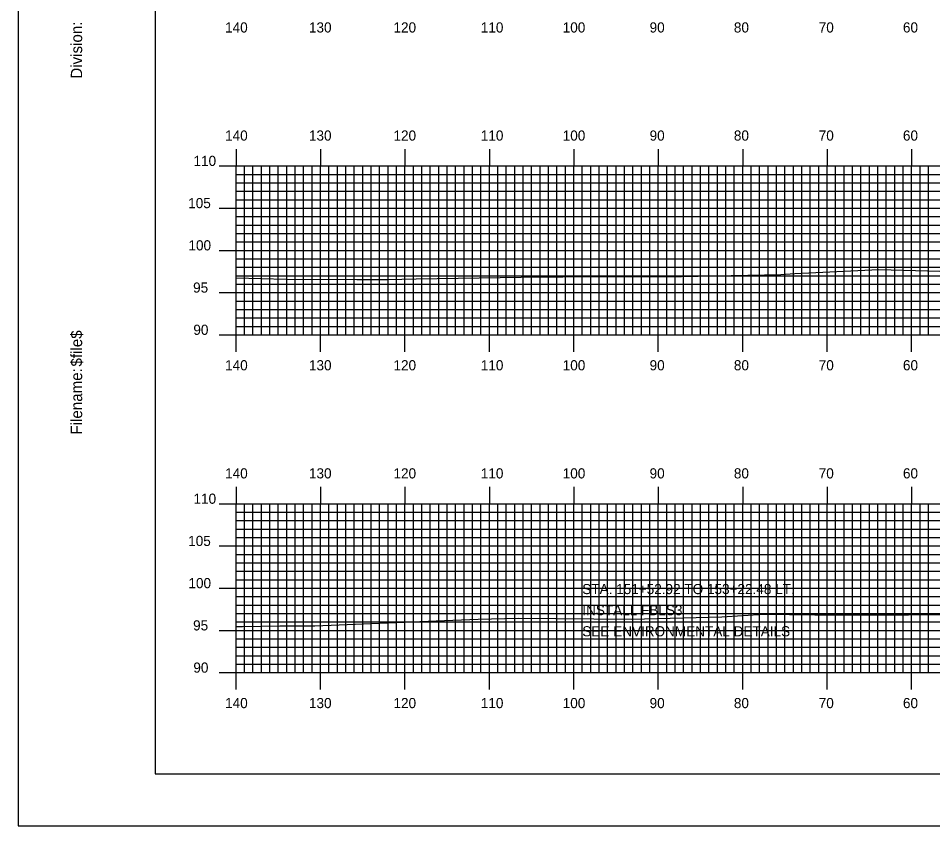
# Model space of a CAD drawing. Extents: x 1778712 to 1779055, y 442591 to 442811.
# Drawn here: x 1778712 to 1778820.3, y 442590.5 to 442686.2 of the extents above; entities that cross this region are included whole.
import ezdxf

# ---------------------------------------------------------------- set-up
doc = ezdxf.new("R2010")
doc.units = 0
for name, color, linetype in [('BORDER', 7, 'Continuous'), ('D_Text_Standard', 7, 'Continuous'), ('H_V ANNOTATION', 7, 'Continuous'), ('MAJOR', 7, 'Continuous'), ('MINOR', 7, 'Continuous'), ('PLOT BOUNDARY', 7, 'Continuous'), ('S_Roadway_Centerline', 7, 'Continuous')]:
    doc.layers.add(name, color=color, linetype=linetype)

msp = doc.modelspace()

# ---------------------------------------------------------------- linework, layer by layer
at = {"layer": 'BORDER'}
msp.add_lwpolyline([(1778728.22, 442596.67), (1779048.22, 442596.67), (1779048.22, 442806.67), (1778728.22, 442806.67)], close=True, dxfattribs=at)
at = {"layer": 'MAJOR'}
for p, q in [((1778737.82, 442670.67), (1778737.82, 442668.67)), ((1778747.82, 442670.67), (1778747.82, 442668.67)), ((1778757.82, 442670.67), (1778757.82, 442668.67)), ((1778767.82, 442670.67), (1778767.82, 442668.67)), ((1778777.82, 442670.67), (1778777.82, 442668.67)), ((1778787.82, 442670.67), (1778787.82, 442668.67)), ((1778797.82, 442670.67), (1778797.82, 442668.67)), ((1778807.82, 442670.67), (1778807.82, 442668.67)), ((1778817.82, 442670.67), (1778817.82, 442668.67)), ((1778735.81, 442668.67), (1778737.82, 442668.67)), ((1778737.82, 442668.67), (1779017.82, 442668.67)), ((1778737.82, 442648.67), (1778737.82, 442668.67)), ((1778737.82, 442648.67), (1778737.82, 442668.67)), ((1778737.82, 442668.67), (1779017.82, 442668.67)), ((1778747.82, 442648.67), (1778747.82, 442668.67)), ((1778757.82, 442648.67), (1778757.82, 442668.67)), ((1778767.82, 442648.67), (1778767.82, 442668.67)), ((1778777.82, 442648.67), (1778777.82, 442668.67)), ((1778787.82, 442648.67), (1778787.82, 442668.67)), ((1778797.82, 442648.67), (1778797.82, 442668.67)), ((1778807.82, 442648.67), (1778807.82, 442668.67)), ((1778817.82, 442648.67), (1778817.82, 442668.67)), ((1778735.81, 442663.67), (1778737.82, 442663.67)), ((1778737.82, 442663.67), (1779017.82, 442663.67)), ((1778735.81, 442658.67), (1778737.82, 442658.67)), ((1778737.82, 442658.67), (1779017.82, 442658.67)), ((1778735.81, 442653.67), (1778737.82, 442653.67)), ((1778737.82, 442653.67), (1779017.82, 442653.67)), ((1778735.81, 442648.67), (1778737.82, 442648.67)), ((1778737.82, 442648.67), (1779017.82, 442648.67)), ((1778737.82, 442648.67), (1779017.82, 442648.67)), ((1778737.82, 442646.66), (1778737.82, 442648.67)), ((1778747.82, 442646.66), (1778747.82, 442648.67)), ((1778757.82, 442646.66), (1778757.82, 442648.67)), ((1778767.82, 442646.66), (1778767.82, 442648.67)), ((1778777.82, 442646.66), (1778777.82, 442648.67)), ((1778787.82, 442646.66), (1778787.82, 442648.67)), ((1778797.82, 442646.66), (1778797.82, 442648.67)), ((1778807.82, 442646.66), (1778807.82, 442648.67)), ((1778817.82, 442646.66), (1778817.82, 442648.67)), ((1778737.82, 442630.67), (1778737.82, 442628.67)), ((1778747.82, 442630.67), (1778747.82, 442628.67)), ((1778757.82, 442630.67), (1778757.82, 442628.67)), ((1778767.82, 442630.67), (1778767.82, 442628.67)), ((1778777.82, 442630.67), (1778777.82, 442628.67)), ((1778787.82, 442630.67), (1778787.82, 442628.67)), ((1778797.82, 442630.67), (1778797.82, 442628.67)), ((1778807.82, 442630.67), (1778807.82, 442628.67)), ((1778817.82, 442630.67), (1778817.82, 442628.67)), ((1778735.81, 442628.67), (1778737.82, 442628.67)), ((1778737.82, 442628.67), (1779017.82, 442628.67)), ((1778737.82, 442608.67), (1778737.82, 442628.67)), ((1778737.82, 442608.67), (1778737.82, 442628.67)), ((1778737.82, 442628.67), (1779017.82, 442628.67)), ((1778747.82, 442608.67), (1778747.82, 442628.67)), ((1778757.82, 442608.67), (1778757.82, 442628.67)), ((1778767.82, 442608.67), (1778767.82, 442628.67)), ((1778777.82, 442608.67), (1778777.82, 442628.67)), ((1778787.82, 442608.67), (1778787.82, 442628.67)), ((1778797.82, 442608.67), (1778797.82, 442628.67)), ((1778807.82, 442608.67), (1778807.82, 442628.67)), ((1778817.82, 442608.67), (1778817.82, 442628.67)), ((1778735.81, 442623.67), (1778737.82, 442623.67)), ((1778737.82, 442623.67), (1779017.82, 442623.67)), ((1778735.81, 442618.67), (1778737.82, 442618.67)), ((1778737.82, 442618.67), (1779017.82, 442618.67)), ((1778735.81, 442613.67), (1778737.82, 442613.67)), ((1778737.82, 442613.67), (1779017.82, 442613.67)), ((1778735.81, 442608.67), (1778737.82, 442608.67)), ((1778737.82, 442608.67), (1779017.82, 442608.67)), ((1778737.82, 442608.67), (1779017.82, 442608.67)), ((1778737.82, 442606.66), (1778737.82, 442608.67)), ((1778747.82, 442606.66), (1778747.82, 442608.67)), ((1778757.82, 442606.66), (1778757.82, 442608.67)), ((1778767.82, 442606.66), (1778767.82, 442608.67)), ((1778777.82, 442606.66), (1778777.82, 442608.67)), ((1778787.82, 442606.66), (1778787.82, 442608.67)), ((1778797.82, 442606.66), (1778797.82, 442608.67)), ((1778807.82, 442606.66), (1778807.82, 442608.67)), ((1778817.82, 442606.66), (1778817.82, 442608.67))]:
    msp.add_line(p, q, dxfattribs=at)
at = {"layer": 'MINOR'}
for p, q in [((1778738.82, 442648.67), (1778738.82, 442668.67)), ((1778739.82, 442648.67), (1778739.82, 442668.67)), ((1778740.82, 442648.67), (1778740.82, 442668.67)), ((1778741.82, 442648.67), (1778741.82, 442668.67)), ((1778742.82, 442648.67), (1778742.82, 442668.67)), ((1778743.82, 442648.67), (1778743.82, 442668.67)), ((1778744.82, 442648.67), (1778744.82, 442668.67)), ((1778745.82, 442648.67), (1778745.82, 442668.67)), ((1778746.82, 442648.67), (1778746.82, 442668.67)), ((1778748.82, 442648.67), (1778748.82, 442668.67)), ((1778749.82, 442648.67), (1778749.82, 442668.67)), ((1778750.82, 442648.67), (1778750.82, 442668.67)), ((1778751.82, 442648.67), (1778751.82, 442668.67)), ((1778752.82, 442648.67), (1778752.82, 442668.67)), ((1778753.82, 442648.67), (1778753.82, 442668.67)), ((1778754.82, 442648.67), (1778754.82, 442668.67)), ((1778755.82, 442648.67), (1778755.82, 442668.67)), ((1778756.82, 442648.67), (1778756.82, 442668.67)), ((1778758.82, 442648.67), (1778758.82, 442668.67)), ((1778759.82, 442648.67), (1778759.82, 442668.67)), ((1778760.82, 442648.67), (1778760.82, 442668.67)), ((1778761.82, 442648.67), (1778761.82, 442668.67)), ((1778762.82, 442648.67), (1778762.82, 442668.67)), ((1778763.82, 442648.67), (1778763.82, 442668.67)), ((1778764.82, 442648.67), (1778764.82, 442668.67)), ((1778765.82, 442648.67), (1778765.82, 442668.67)), ((1778766.82, 442648.67), (1778766.82, 442668.67)), ((1778768.82, 442648.67), (1778768.82, 442668.67)), ((1778769.82, 442648.67), (1778769.82, 442668.67)), ((1778770.82, 442648.67), (1778770.82, 442668.67)), ((1778771.82, 442648.67), (1778771.82, 442668.67)), ((1778772.82, 442648.67), (1778772.82, 442668.67)), ((1778773.82, 442648.67), (1778773.82, 442668.67)), ((1778774.82, 442648.67), (1778774.82, 442668.67)), ((1778775.82, 442648.67), (1778775.82, 442668.67)), ((1778776.82, 442648.67), (1778776.82, 442668.67)), ((1778778.82, 442648.67), (1778778.82, 442668.67)), ((1778779.82, 442648.67), (1778779.82, 442668.67)), ((1778780.82, 442648.67), (1778780.82, 442668.67)), ((1778781.82, 442648.67), (1778781.82, 442668.67)), ((1778782.82, 442648.67), (1778782.82, 442668.67)), ((1778783.82, 442648.67), (1778783.82, 442668.67)), ((1778784.82, 442648.67), (1778784.82, 442668.67)), ((1778785.82, 442648.67), (1778785.82, 442668.67)), ((1778786.82, 442648.67), (1778786.82, 442668.67)), ((1778788.82, 442648.67), (1778788.82, 442668.67)), ((1778789.82, 442648.67), (1778789.82, 442668.67)), ((1778790.82, 442648.67), (1778790.82, 442668.67)), ((1778791.82, 442648.67), (1778791.82, 442668.67)), ((1778792.82, 442648.67), (1778792.82, 442668.67)), ((1778793.82, 442648.67), (1778793.82, 442668.67)), ((1778794.82, 442648.67), (1778794.82, 442668.67)), ((1778795.82, 442648.67), (1778795.82, 442668.67)), ((1778796.82, 442648.67), (1778796.82, 442668.67)), ((1778798.82, 442648.67), (1778798.82, 442668.67)), ((1778799.82, 442648.67), (1778799.82, 442668.67)), ((1778800.82, 442648.67), (1778800.82, 442668.67)), ((1778801.82, 442648.67), (1778801.82, 442668.67)), ((1778802.82, 442648.67), (1778802.82, 442668.67)), ((1778803.82, 442648.67), (1778803.82, 442668.67)), ((1778804.82, 442648.67), (1778804.82, 442668.67)), ((1778805.82, 442648.67), (1778805.82, 442668.67)), ((1778806.82, 442648.67), (1778806.82, 442668.67)), ((1778808.82, 442648.67), (1778808.82, 442668.67)), ((1778809.82, 442648.67), (1778809.82, 442668.67)), ((1778810.82, 442648.67), (1778810.82, 442668.67)), ((1778811.82, 442648.67), (1778811.82, 442668.67)), ((1778812.82, 442648.67), (1778812.82, 442668.67)), ((1778813.82, 442648.67), (1778813.82, 442668.67)), ((1778814.82, 442648.67), (1778814.82, 442668.67)), ((1778815.82, 442648.67), (1778815.82, 442668.67)), ((1778816.82, 442648.67), (1778816.82, 442668.67)), ((1778818.82, 442648.67), (1778818.82, 442668.67)), ((1778819.82, 442648.67), (1778819.82, 442668.67)), ((1778737.82, 442667.67), (1779017.82, 442667.67)), ((1778737.82, 442667.67), (1778739.82, 442667.67)), ((1778737.82, 442666.67), (1779017.82, 442666.67)), ((1778737.82, 442666.67), (1778739.82, 442666.67)), ((1778737.82, 442665.67), (1779017.82, 442665.67)), ((1778737.82, 442665.67), (1778739.82, 442665.67)), ((1778737.82, 442664.67), (1779017.82, 442664.67)), ((1778737.82, 442664.67), (1778739.82, 442664.67)), ((1778737.82, 442662.67), (1779017.82, 442662.67)), ((1778737.82, 442662.67), (1778739.82, 442662.67)), ((1778737.82, 442661.67), (1779017.82, 442661.67)), ((1778737.82, 442661.67), (1778739.82, 442661.67)), ((1778737.82, 442660.67), (1779017.82, 442660.67)), ((1778737.82, 442660.67), (1778739.82, 442660.67)), ((1778737.82, 442659.67), (1779017.82, 442659.67)), ((1778737.82, 442659.67), (1778739.82, 442659.67)), ((1778737.82, 442657.67), (1779017.82, 442657.67)), ((1778737.82, 442657.67), (1778739.82, 442657.67)), ((1778737.82, 442656.67), (1779017.82, 442656.67)), ((1778737.82, 442656.67), (1778739.82, 442656.67)), ((1778737.82, 442655.67), (1779017.82, 442655.67)), ((1778737.82, 442655.67), (1778739.82, 442655.67)), ((1778737.82, 442654.67), (1779017.82, 442654.67)), ((1778737.82, 442654.67), (1778739.82, 442654.67)), ((1778737.82, 442652.67), (1779017.82, 442652.67)), ((1778737.82, 442652.67), (1778739.82, 442652.67)), ((1778737.82, 442651.67), (1779017.82, 442651.67)), ((1778737.82, 442651.67), (1778739.82, 442651.67)), ((1778737.82, 442650.67), (1779017.82, 442650.67)), ((1778737.82, 442650.67), (1778739.82, 442650.67)), ((1778737.82, 442649.67), (1779017.82, 442649.67)), ((1778737.82, 442649.67), (1778739.82, 442649.67)), ((1778738.82, 442608.67), (1778738.82, 442628.67)), ((1778739.82, 442608.67), (1778739.82, 442628.67)), ((1778740.82, 442608.67), (1778740.82, 442628.67)), ((1778741.82, 442608.67), (1778741.82, 442628.67)), ((1778742.82, 442608.67), (1778742.82, 442628.67)), ((1778743.82, 442608.67), (1778743.82, 442628.67)), ((1778744.82, 442608.67), (1778744.82, 442628.67)), ((1778745.82, 442608.67), (1778745.82, 442628.67)), ((1778746.82, 442608.67), (1778746.82, 442628.67)), ((1778748.82, 442608.67), (1778748.82, 442628.67)), ((1778749.82, 442608.67), (1778749.82, 442628.67)), ((1778750.82, 442608.67), (1778750.82, 442628.67)), ((1778751.82, 442608.67), (1778751.82, 442628.67)), ((1778752.82, 442608.67), (1778752.82, 442628.67)), ((1778753.82, 442608.67), (1778753.82, 442628.67)), ((1778754.82, 442608.67), (1778754.82, 442628.67)), ((1778755.82, 442608.67), (1778755.82, 442628.67)), ((1778756.82, 442608.67), (1778756.82, 442628.67)), ((1778758.82, 442608.67), (1778758.82, 442628.67)), ((1778759.82, 442608.67), (1778759.82, 442628.67)), ((1778760.82, 442608.67), (1778760.82, 442628.67)), ((1778761.82, 442608.67), (1778761.82, 442628.67)), ((1778762.82, 442608.67), (1778762.82, 442628.67)), ((1778763.82, 442608.67), (1778763.82, 442628.67)), ((1778764.82, 442608.67), (1778764.82, 442628.67)), ((1778765.82, 442608.67), (1778765.82, 442628.67)), ((1778766.82, 442608.67), (1778766.82, 442628.67)), ((1778768.82, 442608.67), (1778768.82, 442628.67)), ((1778769.82, 442608.67), (1778769.82, 442628.67)), ((1778770.82, 442608.67), (1778770.82, 442628.67)), ((1778771.82, 442608.67), (1778771.82, 442628.67)), ((1778772.82, 442608.67), (1778772.82, 442628.67)), ((1778773.82, 442608.67), (1778773.82, 442628.67)), ((1778774.82, 442608.67), (1778774.82, 442628.67)), ((1778775.82, 442608.67), (1778775.82, 442628.67)), ((1778776.82, 442608.67), (1778776.82, 442628.67)), ((1778778.82, 442608.67), (1778778.82, 442628.67)), ((1778779.82, 442608.67), (1778779.82, 442628.67)), ((1778780.82, 442608.67), (1778780.82, 442628.67)), ((1778781.82, 442608.67), (1778781.82, 442628.67)), ((1778782.82, 442608.67), (1778782.82, 442628.67)), ((1778783.82, 442608.67), (1778783.82, 442628.67)), ((1778784.82, 442608.67), (1778784.82, 442628.67)), ((1778785.82, 442608.67), (1778785.82, 442628.67)), ((1778786.82, 442608.67), (1778786.82, 442628.67)), ((1778788.82, 442608.67), (1778788.82, 442628.67)), ((1778789.82, 442608.67), (1778789.82, 442628.67)), ((1778790.82, 442608.67), (1778790.82, 442628.67)), ((1778791.82, 442608.67), (1778791.82, 442628.67)), ((1778792.82, 442608.67), (1778792.82, 442628.67)), ((1778793.82, 442608.67), (1778793.82, 442628.67)), ((1778794.82, 442608.67), (1778794.82, 442628.67)), ((1778795.82, 442608.67), (1778795.82, 442628.67)), ((1778796.82, 442608.67), (1778796.82, 442628.67)), ((1778798.82, 442608.67), (1778798.82, 442628.67)), ((1778799.82, 442608.67), (1778799.82, 442628.67)), ((1778800.82, 442608.67), (1778800.82, 442628.67)), ((1778801.82, 442608.67), (1778801.82, 442628.67)), ((1778802.82, 442608.67), (1778802.82, 442628.67)), ((1778803.82, 442608.67), (1778803.82, 442628.67)), ((1778804.82, 442608.67), (1778804.82, 442628.67)), ((1778805.82, 442608.67), (1778805.82, 442628.67)), ((1778806.82, 442608.67), (1778806.82, 442628.67)), ((1778808.82, 442608.67), (1778808.82, 442628.67)), ((1778809.82, 442608.67), (1778809.82, 442628.67)), ((1778810.82, 442608.67), (1778810.82, 442628.67)), ((1778811.82, 442608.67), (1778811.82, 442628.67)), ((1778812.82, 442608.67), (1778812.82, 442628.67)), ((1778813.82, 442608.67), (1778813.82, 442628.67)), ((1778814.82, 442608.67), (1778814.82, 442628.67)), ((1778815.82, 442608.67), (1778815.82, 442628.67)), ((1778816.82, 442608.67), (1778816.82, 442628.67)), ((1778818.82, 442608.67), (1778818.82, 442628.67)), ((1778819.82, 442608.67), (1778819.82, 442628.67)), ((1778737.82, 442627.67), (1779017.82, 442627.67)), ((1778737.82, 442627.67), (1778739.82, 442627.67)), ((1778737.82, 442626.67), (1779017.82, 442626.67)), ((1778737.82, 442626.67), (1778739.82, 442626.67)), ((1778737.82, 442625.67), (1779017.82, 442625.67)), ((1778737.82, 442625.67), (1778739.82, 442625.67)), ((1778737.82, 442624.67), (1779017.82, 442624.67)), ((1778737.82, 442624.67), (1778739.82, 442624.67)), ((1778737.82, 442622.67), (1779017.82, 442622.67)), ((1778737.82, 442622.67), (1778739.82, 442622.67)), ((1778737.82, 442621.67), (1779017.82, 442621.67)), ((1778737.82, 442621.67), (1778739.82, 442621.67)), ((1778737.82, 442620.67), (1779017.82, 442620.67)), ((1778737.82, 442620.67), (1778739.82, 442620.67)), ((1778737.82, 442619.67), (1779017.82, 442619.67)), ((1778737.82, 442619.67), (1778739.82, 442619.67)), ((1778737.82, 442617.67), (1779017.82, 442617.67)), ((1778737.82, 442617.67), (1778739.82, 442617.67)), ((1778737.82, 442616.67), (1779017.82, 442616.67)), ((1778737.82, 442616.67), (1778739.82, 442616.67)), ((1778737.82, 442615.67), (1779017.82, 442615.67)), ((1778737.82, 442615.67), (1778739.82, 442615.67)), ((1778737.82, 442614.67), (1779017.82, 442614.67)), ((1778737.82, 442614.67), (1778739.82, 442614.67)), ((1778737.82, 442612.67), (1779017.82, 442612.67)), ((1778737.82, 442612.67), (1778739.82, 442612.67)), ((1778737.82, 442611.67), (1779017.82, 442611.67)), ((1778737.82, 442611.67), (1778739.82, 442611.67)), ((1778737.82, 442610.67), (1779017.82, 442610.67)), ((1778737.82, 442610.67), (1778739.82, 442610.67)), ((1778737.82, 442609.67), (1779017.82, 442609.67)), ((1778737.82, 442609.67), (1778739.82, 442609.67))]:
    msp.add_line(p, q, dxfattribs=at)
at = {"layer": 'PLOT BOUNDARY'}
msp.add_lwpolyline([(1778712.03, 442590.55), (1779052.03, 442590.55), (1779052.03, 442810.55), (1778712.03, 442810.55)], close=True, dxfattribs=at)
at = {"layer": 'S_Roadway_Centerline'}
for points in [[(1778737.82, 442655.41), (1778743.77, 442655.28), (1778752.12, 442655.24), (1778755.74, 442655.24), (1778759.16, 442655.3), (1778771.59, 442655.5), (1778781.49, 442655.56), (1778790.56, 442655.57), (1778800.38, 442655.77), (1778802.33, 442655.8), (1778803.98, 442655.93), (1778813.95, 442656.4), (1778826.91, 442656.05)], [(1778737.82, 442614.14), (1778738.57, 442614.15), (1778742.99, 442614.22), (1778747.13, 442614.23), (1778761.51, 442614.82), (1778766.49, 442614.99), (1778771.23, 442615.13), (1778784.66, 442614.99), (1778795.36, 442615.27), (1778800.31, 442615.6), (1778806.34, 442615.52), (1778817.44, 442615.53), (1778827.84, 442615.54)]]:
    msp.add_lwpolyline(points, dxfattribs=at)

# ---------------------------------------------------------------- texts
at = {"layer": 'BORDER'}
for s, p in [('Division:', (1778719.59, 442679)), ('$file$', (1778719.59, 442644.92)), ('Filename:', (1778719.59, 442636.86))]:
    msp.add_text(s, height=1.339, rotation=90, dxfattribs=at).set_placement(p)
at = {"layer": 'D_Text_Standard'}
for s, p in [('STA. 151+52.92 TO 153+22.48 LT.', (1778778.82, 442617.97)), ('INSTALL FBLS3', (1778778.82, 442615.47)), ('SEE ENVIRONMENTAL DETAILS', (1778778.82, 442612.97))]:
    msp.add_text(s, height=1.2, dxfattribs=at).set_placement(p)
at = {"layer": 'H_V ANNOTATION'}
for s, p in [('140', (1778736.52, 442684.47)), ('130', (1778746.45, 442684.47)), ('120', (1778756.46, 442684.47)), ('110', (1778766.8, 442684.47)), ('100', (1778776.5, 442684.47)), ('90', (1778786.79, 442684.47)), ('80', (1778796.77, 442684.47)), ('70', (1778806.82, 442684.47)), ('60', (1778816.79, 442684.47)), ('140', (1778736.52, 442671.67)), ('130', (1778746.45, 442671.67)), ('120', (1778756.46, 442671.67)), ('110', (1778766.8, 442671.67)), ('100', (1778776.5, 442671.67)), ('90', (1778786.79, 442671.67)), ('80', (1778796.77, 442671.67)), ('70', (1778806.82, 442671.67)), ('60', (1778816.79, 442671.67)), ('110', (1778732.78, 442668.67)), ('105', (1778732.15, 442663.67)), ('100', (1778732.18, 442658.67)), ('95', (1778732.73, 442653.67)), ('90', (1778732.76, 442648.67)), ('140', (1778736.52, 442644.47)), ('130', (1778746.45, 442644.47)), ('120', (1778756.46, 442644.47)), ('110', (1778766.8, 442644.47)), ('100', (1778776.5, 442644.47)), ('90', (1778786.79, 442644.47)), ('80', (1778796.77, 442644.47)), ('70', (1778806.82, 442644.47)), ('60', (1778816.79, 442644.47)), ('140', (1778736.52, 442631.67)), ('130', (1778746.45, 442631.67)), ('120', (1778756.46, 442631.67)), ('110', (1778766.8, 442631.67)), ('100', (1778776.5, 442631.67)), ('90', (1778786.79, 442631.67)), ('80', (1778796.77, 442631.67)), ('70', (1778806.82, 442631.67)), ('60', (1778816.79, 442631.67)), ('110', (1778732.78, 442628.67)), ('105', (1778732.15, 442623.67)), ('100', (1778732.18, 442618.67)), ('95', (1778732.73, 442613.67)), ('90', (1778732.76, 442608.67)), ('140', (1778736.52, 442604.47)), ('130', (1778746.45, 442604.47)), ('120', (1778756.46, 442604.47)), ('110', (1778766.8, 442604.47)), ('100', (1778776.5, 442604.47)), ('90', (1778786.79, 442604.47)), ('80', (1778796.77, 442604.47)), ('70', (1778806.82, 442604.47)), ('60', (1778816.79, 442604.47))]:
    msp.add_text(s, height=1.2, dxfattribs=at).set_placement(p)
at = {"layer": 'MAJOR'}
for p in [(1778737.81, 442648.67), (1778737.81, 442608.67)]:
    msp.add_text('-', height=0.012, dxfattribs=at).set_placement(p)

doc.saveas('drawing.dxf')
